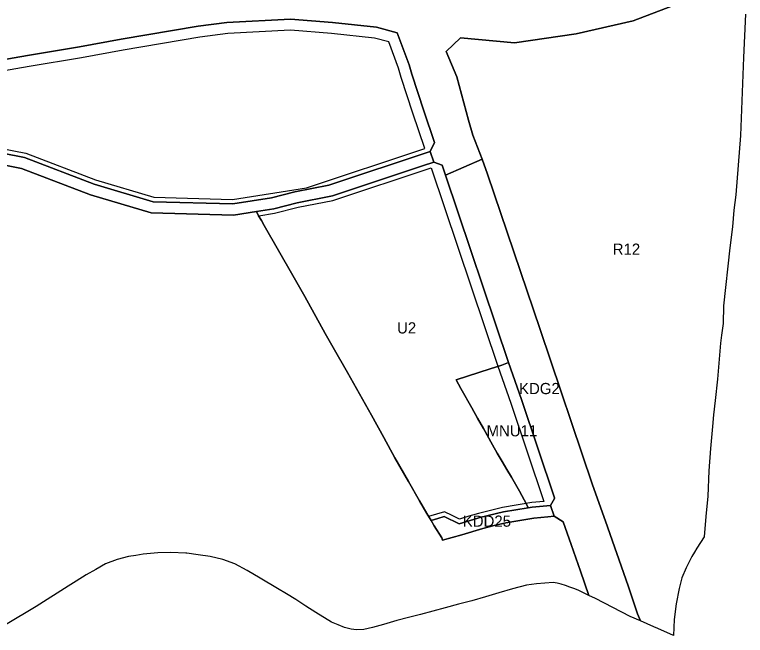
# Model space of a CAD drawing. Extents: x 7440055 to 7442242, y 5549003 to 5552256.
# Drawn here: x 7441405 to 7442059, y 5549108 to 5549663 of the extents above; entities that cross this region are included whole.
import ezdxf

# ---------------------------------------------------------------- set-up
doc = ezdxf.new("R2010")
doc.units = 0
for name, color, linetype in [('linie_rozgraniczajace', 7, 'Continuous'), ('linie_zabudowy_nieprzekraczalne', 7, 'Continuous'), ('oznaczenia_przeznaczen', 7, 'Continuous')]:
    doc.layers.add(name, color=color, linetype=linetype)

msp = doc.modelspace()

# ---------------------------------------------------------------- linework, layer by layer
at = {"layer": 'linie_rozgraniczajace'}
for points in [[(7442043.62, 5549690.55), (7441958.36, 5549657.75), (7441907.4, 5549646.04), (7441852.41, 5549638.18), (7441803.93, 5549642.67), (7441791.23, 5549630.35), (7441800.7, 5549607.72), (7441811.15, 5549568.97), (7441815.19, 5549555.68), (7441823.29, 5549534.08), (7441790.63, 5549519.87), (7441787.69, 5549528.62), (7441780.02, 5549531.43), (7441776.88, 5549540.92), (7441780.85, 5549549.1), (7441771.34, 5549577.41), (7441760.38, 5549610.03), (7441758.07, 5549618.54), (7441747.49, 5549647.2), (7441728.99, 5549652.19), (7441689.57, 5549656.35), (7441652.08, 5549659.32), (7441595.04, 5549656.32), (7441569.29, 5549653.04), (7441500.52, 5549641.39), (7441463.38, 5549634.65), (7441416.63, 5549626.68), (7441380.59, 5549620.51)], [(7442058.8, 5549663.73), (7442057.24, 5549624.99), (7442054.44, 5549555.36), (7442052.42, 5549528.8), (7442050.39, 5549502.24), (7442048.61, 5549488.41), (7442047.22, 5549473.64), (7442044.93, 5549454.76), (7442039.29, 5549403.04), (7442038.99, 5549387.13), (7442037.29, 5549376.75), (7442036.46, 5549369.54), (7442033.88, 5549337.57), (7442031.82, 5549318.37), (7442030.36, 5549305.65), (7442029.27, 5549295.17), (7442027.65, 5549275.32), (7442026.04, 5549255.47), (7442025.09, 5549232.87), (7442023.49, 5549214.71), (7442021.9, 5549196.56), (7442015.49, 5549186.47), (7442013.25, 5549182.66), (7442011, 5549178.84), (7442005.7, 5549168.86), (7442001.97, 5549159.71), (7441999.64, 5549150.41), (7441996.86, 5549136.48), (7441995.22, 5549122.66), (7441994.59, 5549108.37), (7441980.61, 5549114.41), (7441977.03, 5549115.96), (7441964.85, 5549121.23), (7441962.32, 5549127.7), (7441953.88, 5549152.67), (7441933.73, 5549210.36), (7441922.01, 5549243.08), (7441875.14, 5549381.95), (7441828.26, 5549520.83), (7441823.29, 5549534.08), (7441815.19, 5549555.68), (7441811.15, 5549568.97), (7441800.7, 5549607.72), (7441791.23, 5549630.35), (7441803.93, 5549642.67), (7441852.41, 5549638.18), (7441907.4, 5549646.04), (7441958.36, 5549657.75), (7442043.62, 5549690.55)], [(7441380.59, 5549620.51), (7441416.63, 5549626.68), (7441463.38, 5549634.65), (7441500.52, 5549641.39), (7441569.29, 5549653.04), (7441595.04, 5549656.32), (7441652.08, 5549659.32), (7441689.57, 5549656.35), (7441728.99, 5549652.19), (7441747.49, 5549647.2), (7441758.07, 5549618.54), (7441760.38, 5549610.03), (7441771.34, 5549577.41), (7441780.85, 5549549.1), (7441776.88, 5549540.92), (7441686.23, 5549510.82), (7441655.79, 5549504.86), (7441634.92, 5549499.47), (7441600.33, 5549494.08), (7441529.02, 5549496.06), (7441476.28, 5549511.8), (7441414.05, 5549535.54), (7441321.31, 5549553.68)], [(7441321.31, 5549553.68), (7441414.05, 5549535.54), (7441476.28, 5549511.8), (7441529.02, 5549496.06), (7441600.33, 5549494.08), (7441634.92, 5549499.47), (7441655.79, 5549504.86), (7441686.23, 5549510.82), (7441776.88, 5549540.92), (7441780.02, 5549531.43), (7441770.1, 5549528.11), (7441748.49, 5549520.94), (7441705.7, 5549506.75), (7441689.41, 5549501.26), (7441688.16, 5549501.01), (7441658.01, 5549495.1), (7441636.94, 5549489.67), (7441621.42, 5549487.25), (7441600.97, 5549484.06), (7441527.42, 5549486.1), (7441473.07, 5549502.32), (7441411.29, 5549525.89), (7441320.72, 5549543.6)], [(7441320.72, 5549543.6), (7441411.29, 5549525.89), (7441473.07, 5549502.32), (7441527.42, 5549486.1), (7441600.97, 5549484.06), (7441621.42, 5549487.25), (7441623.49, 5549483.6), (7441625.98, 5549479.18), (7441628.47, 5549474.76), (7441654.16, 5549430.14), (7441664.84, 5549411.23), (7441683.11, 5549378.29), (7441690.05, 5549365.82), (7441702.87, 5549343.5), (7441724.43, 5549305.21), (7441735.33, 5549285.39), (7441745.4, 5549267.22), (7441757.36, 5549245.93), (7441767.33, 5549228.51), (7441773.86, 5549217.24)], [(7441773.86, 5549217.24), (7441777.68, 5549211), (7441780.52, 5549206.36), (7441787.19, 5549195.48), (7441787.84, 5549193.4), (7441796.5, 5549195.85), (7441805.15, 5549198.3), (7441824, 5549204), (7441834.26, 5549206.52), (7441844.51, 5549209.04), (7441857.01, 5549211.09), (7441869.5, 5549213.13), (7441882.2, 5549214.34), (7441887.65, 5549214.86), (7441895.69, 5549209.82), (7441902.96, 5549189.5), (7441911.45, 5549165.81), (7441918.78, 5549144.1), (7441916.89, 5549145.02), (7441909.12, 5549148.75), (7441905.41, 5549150.15), (7441901.71, 5549151.54), (7441897.89, 5549152.92), (7441894.08, 5549154.3), (7441890.47, 5549154.91), (7441886.85, 5549155.53), (7441879.56, 5549155.07), (7441871.93, 5549154.45), (7441862.9, 5549153.27), (7441850.66, 5549149.88), (7441838.41, 5549146.48), (7441826.28, 5549142.88), (7441814.14, 5549139.27), (7441802.26, 5549136.14), (7441790.39, 5549133.01), (7441779.31, 5549129.96), (7441768.24, 5549126.9), (7441757.65, 5549124.34), (7441747.06, 5549121.77), (7441735.04, 5549118.2), (7441725.31, 5549115.36), (7441721.4, 5549114.52), (7441717.49, 5549113.69), (7441711.11, 5549113.3), (7441706.19, 5549113.85), (7441700.2, 5549115.46), (7441694.49, 5549117.78), (7441688.78, 5549120.1), (7441674.51, 5549128.85), (7441665.56, 5549134.62), (7441656.62, 5549140.4), (7441648.51, 5549145.4), (7441640.41, 5549150.4), (7441624.98, 5549159.54), (7441613.11, 5549166.34), (7441602.16, 5549172.44), (7441591.41, 5549176.1), (7441580.24, 5549178.93), (7441569.4, 5549180.48), (7441559.2, 5549181.77), (7441558.3, 5549181.88), (7441544.89, 5549182.47), (7441533.35, 5549182.03), (7441520.17, 5549180.93), (7441513.7, 5549179.84), (7441507.22, 5549178.76), (7441496.98, 5549176.27), (7441486.63, 5549172.27), (7441477.92, 5549167.36), (7441469.21, 5549162.46), (7441460.29, 5549156.83), (7441453.21, 5549152.38), (7441424.45, 5549134.26), (7441396.95, 5549117.87)]]:
    msp.add_lwpolyline(points, dxfattribs=at)
for points in [[(7441790.63, 5549519.87), (7441823.29, 5549534.08), (7441828.26, 5549520.83), (7441875.14, 5549381.95), (7441922.01, 5549243.08), (7441933.73, 5549210.36), (7441953.88, 5549152.67), (7441962.32, 5549127.7), (7441964.85, 5549121.23), (7441955.83, 5549125.12), (7441924.65, 5549141.28), (7441918.78, 5549144.1), (7441911.45, 5549165.81), (7441902.96, 5549189.5), (7441895.69, 5549209.82), (7441887.65, 5549214.86), (7441884.44, 5549224.6), (7441888.16, 5549230.83), (7441888.01, 5549231.25), (7441858.49, 5549319.27), (7441846.93, 5549352.32)], [(7441621.42, 5549487.25), (7441636.94, 5549489.67), (7441658.01, 5549495.1), (7441688.16, 5549501.01), (7441689.41, 5549501.26), (7441705.7, 5549506.75), (7441748.49, 5549520.94), (7441770.1, 5549528.11), (7441780.02, 5549531.43), (7441787.69, 5549528.62), (7441790.63, 5549519.87), (7441846.93, 5549352.32), (7441843.92, 5549351.06), (7441840.91, 5549349.8), (7441830.68, 5549346.54), (7441810.22, 5549340.03), (7441799.99, 5549336.78), (7441804.43, 5549329.07), (7441814.12, 5549311.8), (7441819.31, 5549302.51), (7441824.5, 5549293.22), (7441832.67, 5549278.87), (7441836.92, 5549271.35), (7441841.17, 5549263.82), (7441845.38, 5549256.78), (7441849.59, 5549249.73), (7441853.16, 5549243.49), (7441856.72, 5549237.26), (7441858.91, 5549233.34), (7441861.09, 5549229.41), (7441862.14, 5549227.38), (7441864.67, 5549222.48), (7441842.51, 5549218.84), (7441821.36, 5549213.65), (7441819.66, 5549213.14), (7441802.76, 5549208.14), (7441789.5, 5549214.58), (7441783.63, 5549212.8), (7441777.68, 5549211), (7441773.86, 5549217.24), (7441767.33, 5549228.51), (7441757.36, 5549245.93), (7441745.4, 5549267.22), (7441735.33, 5549285.39), (7441724.43, 5549305.21), (7441702.87, 5549343.5), (7441690.05, 5549365.82), (7441683.11, 5549378.29), (7441664.84, 5549411.23), (7441654.16, 5549430.14), (7441628.47, 5549474.76), (7441625.98, 5549479.18), (7441623.49, 5549483.6)], [(7441799.99, 5549336.78), (7441810.22, 5549340.03), (7441830.68, 5549346.54), (7441840.91, 5549349.8), (7441843.92, 5549351.06), (7441846.93, 5549352.32), (7441858.49, 5549319.27), (7441888.01, 5549231.25), (7441888.16, 5549230.83), (7441884.44, 5549224.6), (7441868.22, 5549223.06), (7441864.67, 5549222.48), (7441862.14, 5549227.38), (7441861.09, 5549229.41), (7441858.91, 5549233.34), (7441856.72, 5549237.26), (7441853.16, 5549243.49), (7441849.59, 5549249.73), (7441845.38, 5549256.78), (7441841.17, 5549263.82), (7441836.92, 5549271.35), (7441832.67, 5549278.87), (7441824.5, 5549293.22), (7441819.31, 5549302.51), (7441814.12, 5549311.8), (7441804.43, 5549329.07)], [(7441777.68, 5549211), (7441783.63, 5549212.8), (7441789.5, 5549214.58), (7441802.76, 5549208.14), (7441819.66, 5549213.14), (7441821.36, 5549213.65), (7441842.51, 5549218.84), (7441864.67, 5549222.48), (7441868.22, 5549223.06), (7441884.44, 5549224.6), (7441887.65, 5549214.86), (7441882.2, 5549214.34), (7441869.5, 5549213.13), (7441857.01, 5549211.09), (7441844.51, 5549209.04), (7441834.26, 5549206.52), (7441824, 5549204), (7441805.15, 5549198.3), (7441796.5, 5549195.85), (7441787.84, 5549193.4), (7441787.19, 5549195.48), (7441780.52, 5549206.36)]]:
    msp.add_lwpolyline(points, close=True, dxfattribs=at)
at = {"layer": 'linie_zabudowy_nieprzekraczalne'}
for points in [[(7441321.55, 5549557.71), (7441415.16, 5549539.4), (7441477.57, 5549515.59), (7441529.65, 5549500.04), (7441600.08, 5549498.09), (7441666.28, 5549508.41), (7441772.16, 5549543.57), (7441761.48, 5549575.36), (7441761.48, 5549575.36), (7441750.81, 5549607.13), (7441748.54, 5549615.5), (7441739.9, 5549638.89), (7441727.15, 5549642.33), (7441688.65, 5549646.39), (7441651.95, 5549649.3), (7441595.93, 5549646.35), (7441570.76, 5549643.14), (7441502.24, 5549631.54), (7441465.11, 5549624.8), (7441418.31, 5549616.82), (7441382.24, 5549610.65)], [(7441623.52, 5549483.53), (7441637.75, 5549485.75), (7441658.89, 5549491.2), (7441689.8, 5549497.26), (7441777.85, 5549526.49), (7441837.5, 5549349.02), (7441849.03, 5549316.03), (7441878.54, 5549228.05), (7441867.71, 5549227.03), (7441841.7, 5549222.76), (7441820.1, 5549217.37), (7441811.61, 5549214.89), (7441803.11, 5549212.41), (7441796.48, 5549215.63), (7441789.84, 5549218.86), (7441782.68, 5549216.69), (7441775.52, 5549214.53)]]:
    msp.add_lwpolyline(points, dxfattribs=at)

# ---------------------------------------------------------------- texts
at = {"layer": 'oznaczenia_przeznaczen'}
for s, p in [('R12', (7441940.17, 5549448.66)), ('U2', (7441747.26, 5549378.29)), ('KDG2', (7441856.36, 5549324.05)), ('MNU11', (7441827.33, 5549286.3)), ('KDD25', (7441806.07, 5549205.5))]:
    msp.add_text(s, height=10, dxfattribs=at).set_placement(p)

doc.saveas('drawing.dxf')
